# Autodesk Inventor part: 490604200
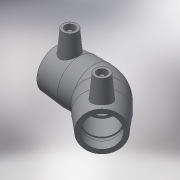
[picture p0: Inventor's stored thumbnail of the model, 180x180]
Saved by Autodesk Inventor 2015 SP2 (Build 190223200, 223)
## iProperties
Created: 2017-06
Part Number: 490604200
Material: Generic
Description: PLASSON 45° ELBOW 200
Document SubType Name: Modeling
Designer: KIM
Mass: 55.0731 g
Surface Area: 148.067 cm^2
Volume: 55.0731 cm^3
Density: 1 g/cm^3
Appearance: Default
Author: KIM
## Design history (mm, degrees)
derived "490604.ipt"
feature "Solid1::490604.ipt"
tag "TaggingFeature1"
body "Solid1"
other parameters: "d2" = 261, "d4" = 118, "d5" = 234.9, "d8" = 168 deg, "d10" = 44.8, "d11" = 14.93333, "d14" = 17.6296, "d19" = 3.52592, "d20" = 168 deg, "d22" = 240.12, "d23" = 261, "d24" = 232.9164, "d29" = 125, "d30" = 15, "d31" = 165.2, "d34" = 5 deg, "d35" = 12, "d39" = 0, "d41" = 4, "d42" = 14, "d43" = 0, "d44" = 9.6, "d45" = 4.8, "d46" = 6, "d47" = 0, "d51" = 44.8, "d52" = 112, "d54" = 135 deg, "d67" = 45 deg, "d71" = 135 deg, "d75" = 13.05, "d82" = 45 deg, "d83" = 112, "d84" = 234.9, "d86" = 117.45, "d87" = 135 deg, "d88" = 472, "d90" = 112, "d91" = 0, "d92" = 112, "d93" = 0, "d94" = 135 deg, "d95" = 120.06, "d98" = 472, "d99" = 155.76, "d101" = 3, "d102" = 0, "d103" = 3, "d104" = 0, "d105" = 32.48, "d106" = 8.12, "L_" = 472, "L_1" = 112, "D_" = 261, "A_" = 125, "d_2" = 12
